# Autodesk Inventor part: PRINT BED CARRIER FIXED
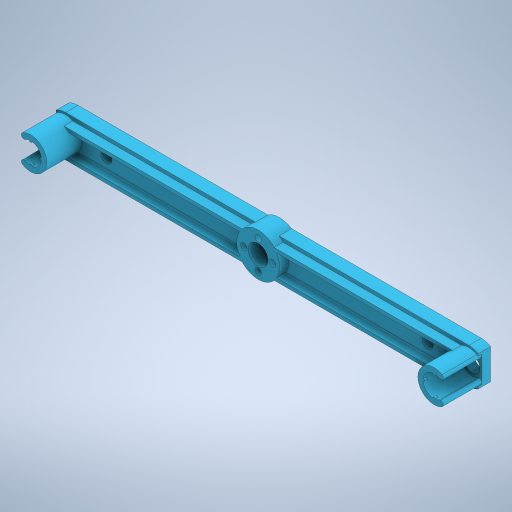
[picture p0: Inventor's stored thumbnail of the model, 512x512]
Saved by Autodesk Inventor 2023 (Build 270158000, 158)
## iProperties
Created: 2025-07
Part Number: PRINT BED CARRIER FIXED
Material: Generic
Document SubType Name: Modeling
Designer: erjon
Density: 1 g/cm^3
Appearance: Turquoise
Author: erjon
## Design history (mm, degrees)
feature "Base1"
sketch "Sketch1"
  geometry: L1 (106.675, 0)-(0, 0) reference; L2 (-12.649, 0)-(-119.325, 0) reference; L3 (-119.325, -18)-(-12.649, -18) reference; L4 (0, -18)-(106.675, -18) reference; C1 r 5.5 at (-6.325, -9) reference; C2 r 3.1 at (83.675, -9) reference; C3 r 3.1 at (-96.325, -9) reference; C4 r 1.75 at (1.675, -9) reference; C5 r 1.75 at (-6.325, -17) reference; C6 r 1.75 at (-14.325, -9) reference; C7 r 1.75 at (-6.325, -1) reference; A1 r 9 centre (106.675, -9) between (106.675, 0) and (106.675, -18) reference; A2 r 11 centre (-6.325, -9) between (0, 0) and (-12.649, 0) reference; A3 r 9 centre (-119.325, -9) between (-119.325, -18) and (-119.325, 0) reference; A4 r 11 centre (-6.325, -9) between (-12.649, -18) and (0, -18) reference; 1 further point
extrude "Extrusion1" join sketch "Sketch1" distance "d0" = 2; taper "d1" = 0 deg
sketch "Sketch2"
  geometry: L1 (-12.649, 0)-(-119.325, 0) reference; L2 (-119.325, -18)-(-12.649, -18) reference; L3 (0, -18)-(106.675, -18) reference; L4 (106.675, 0)-(0, 0) reference; C1 r 5.5 at (-6.325, -9) reference; C2 r 3.1 at (83.675, -9) reference; C3 r 3.1 at (-96.325, -9) reference; C4 r 1.75 at (1.675, -9) reference; C5 r 1.75 at (-14.325, -9) reference; C6 r 1.75 at (-6.325, -1) reference; C7 r 1.75 at (-6.325, -17) reference; C8 r 11 at (-6.325, -9); A1 r 9 centre (-119.325, -9) between (-119.325, -18) and (-119.325, 0) reference; A2 r 11 centre (-6.325, -9) between (-12.649, -18) and (0, -18) reference; A3 r 9 centre (106.675, -9) between (106.675, 0) and (106.675, -18) reference; A4 r 11 centre (-6.325, -9) between (0, 0) and (-12.649, 0) reference; 5 further points
  constraints: 1 centre point, 1 coincident
extrude "Extrusion2" join sketch "Sketch2" distance "d2" = 5; taper "d3" = 0 deg
sketch "Sketch4"
  geometry: L1 (106.675, 0)-(0, 0) reference; L2 (0, 18)-(106.675, 18) reference; L3 (-119.325, 18)-(-12.649, 18) reference; L4 (-12.649, 0)-(-119.325, 0) reference; L5 (106.675, -1)-(0.309, -1); L6 (-12.958, -1)-(-119.325, -1); L7 (-119.325, 19)-(-12.958, 19); L8 (0.309, 19)-(106.675, 19); C1 r 3.1 at (-96.325, 9) reference; C2 r 3.1 at (83.675, 9) reference; C3 r 4.25 at (-119.325, 9) reference; C4 r 1.75 at (-14.325, 9) reference; C5 r 1.75 at (-6.325, 1) reference; C6 r 1.75 at (1.675, 9) reference; C7 r 1.75 at (-6.325, 17) reference; C8 r 4.25 at (-6.325, 9) reference; C9 r 4.25 at (106.675, 9) reference; A1 r 9 centre (106.675, 9) between (106.675, 0) and (106.675, 18) reference; A2 r 11 centre (-6.325, 9) between (0, 18) and (-12.649, 18) reference; A3 r 9 centre (-119.325, 9) between (-119.325, 18) and (-119.325, 0) reference; A4 r 11 centre (-6.325, 9) between (-12.649, 0) and (0, 0) reference; A5 r 10 centre (106.675, 9) between (106.675, -1) and (106.675, 19); A6 r 12 centre (-6.325, 9) between (-12.958, -1) and (0.309, -1); A7 r 10 centre (-119.325, 9) between (-119.325, 19) and (-119.325, -1); A8 r 12 centre (-6.325, 9) between (0.309, 19) and (-12.958, 19); 1 further point
  constraints: 8 end point, 8 point on circle, 4 centre point, 7 other
  dimensions: "d6" = 1 distance between parallel lines of L2 L8
extrude "Extrusion3" join sketch "Sketch4" distance "d7" = 7; taper "d8" = 0 deg
sketch "Sketch5"
  geometry: C1 r 11 at (0, 0) reference; C2 r 1.75 at (0, -8) reference; C3 r 1.75 at (0, 8) reference; C4 r 1.75 at (-8, 0) reference; C5 r 1.75 at (8, 0) reference; C6 r 5.5 at (0, 0) reference; C7 r 12 at (0, 0); 1 further point
  constraints: 1 centre point, 1 coincident
extrude "Extrusion4" join sketch "Sketch5" distance "d9" = 7; taper "d10" = 0 deg
sketch "Sketch6"
  geometry: L1 (83.675, -9)-(83.675, -15); L2 (83.675, -9)-(83.675, -3); L3 (83.675, -3)-(83.675, -1); L4 (83.675, -1)-(105.195, -1); L5 (83.675, -3)-(102.093, -3); L6 (102.093, -3)-(1.227, -3); L7 (1.227, -3)-(1.227, -1); L8 (1.227, -1)-(105.195, -1); L9 (105.195, -1)-(102.093, -3); L10 (-6.325, -9)-(11.463, -9); L11 (102.093, -15)-(1.227, -15); L12 (1.227, -17)-(105.195, -17); L13 (1.227, -15)-(1.227, -17); L14 (105.195, -17)-(102.093, -15); L15 (-6.325, -9)-(-6.325, -12); L16 (-13.876, -1)-(-117.844, -1); L17 (-114.742, -3)-(-13.876, -3); L18 (-13.876, -3)-(-13.876, -1); L19 (-117.844, -1)-(-114.742, -3); L20 (-117.844, -17)-(-114.742, -15); L21 (-114.742, -15)-(-13.876, -15); L22 (-13.876, -17)-(-117.844, -17); L23 (-13.876, -15)-(-13.876, -17); C1 r 3.1 at (83.675, -9) reference; 2 further points
  constraints: 46 end point, 12 symmetric about line, 4 vertical, 2 horizontal, 2 perpendicular, 1 collinear, 1 point on line
  dimensions: "d11" = 6 distance of L1.start L1.end; "d12" = 6 distance of L1.start L2.end; "d13" = 2 distance of L2.end L3.end
extrude "Extrusion5" join sketch "Sketch6" distance "d14" = 5; taper "d15" = 0 deg
sketch "Sketch7"
  geometry: 1 further point
sketch "Sketch8"
  geometry: L1 (5.242, -6.5)-(5.242, 11.624); L2 (5.242, 11.624)-(5.242, -10.396); L3 (-113, 0)-(-113, 17.006); L4 (-231.242, 11.624)-(-231.242, -10.396); L5 (-221.877, 8)-(-121.944, 8) reference; L6 (-119.633, 10)-(-226, 10) reference; L7 (-226, -10)-(-119.633, -10) reference; L8 (-121.944, -8)-(-221.877, -8) reference; L9 (-4.123, -8)-(-104.056, -8) reference; L10 (-106.367, -10)-(0, -10) reference; L11 (0, 10)-(-106.367, 10) reference; L12 (-104.056, 8)-(-4.123, 8) reference; C1 r 4.25 at (-226, 0) reference; C2 r 4.25 at (0, 0) reference; A1 r 1.5 centre (3.742, -6.5) between (4.49, -7.8) and (3.742, -5) reference; A2 r 12 centre (-113, 0) between (-119.633, 10) and (-121.944, 8) reference; A3 r 10 centre (-226, 0) between (-226, 10) and (-226, -10) reference; A4 r 12 centre (-113, 0) between (-121.944, -8) and (-119.633, -10) reference; A5 r 9 centre (-226, 0) between (-230.49, -7.8) and (-221.877, -8) reference; A6 r 9 centre (-226, 0) between (-230.49, 7.8) and (-230.49, -7.8) reference; A7 r 9 centre (-226, 0) between (-221.877, 8) and (-230.49, 7.8) reference; A8 r 6.025 centre (-226, 0) between (-229.037, -5.204) and (-229.037, 5.204) reference; A9 r 1.5 centre (-229.793, 6.499) between (-229.742, 5) and (-229.037, 5.204) reference; A10 r 1.5 centre (-229.742, 6.5) between (-230.49, 7.8) and (-229.742, 5) reference; A11 r 9 centre (-226, 0) between (-230.49, 7.8) and (-230.49, -7.8) reference; A12 r 1.5 centre (-229.742, -6.5) between (-229.742, -5) and (-230.49, -7.8) reference; A13 r 1.5 centre (-229.793, -6.499) between (-229.037, -5.204) and (-229.742, -5) reference; A14 r 1.5 centre (3.742, -6.5) between (4.49, -7.8) and (3.742, -5) reference; A15 r 9 centre (0, 0) between (4.49, -7.8) and (4.49, 7.8) reference; A16 r 1.5 centre (3.742, 6.5) between (3.742, 5) and (4.49, 7.8) reference; A17 r 1.5 centre (3.793, 6.499) between (3.037, 5.204) and (3.742, 5) reference; A18 r 6.025 centre (0, 0) between (3.037, 5.204) and (3.037, -5.204) reference; A19 r 1.5 centre (3.793, -6.499) between (3.742, -5) and (3.037, -5.204) reference; A20 r 10 centre (0, 0) between (0, -10) and (0, 10) reference; A21 r 12 centre (-113, 0) between (-106.367, -10) and (-104.056, -8) reference; A22 r 10 centre (0, 0) between (0, -10) and (0, 10) reference; A23 r 12 centre (-113, 0) between (-104.056, 8) and (-106.367, 10) reference; A24 r 9 centre (0, 0) between (4.49, 7.8) and (-4.123, 8) reference; A25 r 9 centre (0, 0) between (4.49, -7.8) and (4.49, 7.8) reference; A26 r 9 centre (0, 0) between (-4.123, -8) and (4.49, -7.8) reference; 5 further points
  constraints: 8 end point, 2 symmetric about line, 2 vertical, 1 point on circle, 1 point on line, 1 tangent
extrude "Extrusion6" cut sketch "Sketch8" stored distance "d16" = 15; taper "d17" = 0 deg
body "Solid1"
node "Projected Loop1"
node "Projected Loop2"
node "Projected Loop3"
node "Projected Loop4"
node "Projected Loop5"
node "Projected Loop6"
node "Projected Loop7"
node "Projected Loop8"
